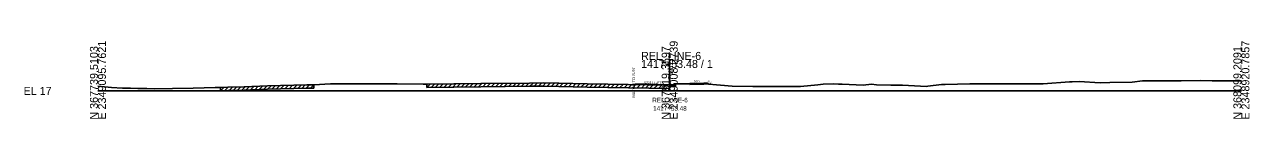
# Model space of a CAD drawing. Extents: x -26 to 403, y -10 to 6565.
# Drawn here: x -25.7 to 402.8, y -9.7 to 17.3 of the extents above; entities that cross this region are included whole.
import ezdxf

# ---------------------------------------------------------------- set-up
doc = ezdxf.new("R2010")
doc.units = 0
for name, color, linetype in [('RD_GPK_XS_Cell', 7, 'Continuous'), ('RD_XS_CurbBase', 7, 'Continuous'), ('RD_XS_CurbFront', 7, 'Continuous'), ('RD_XS_CurbTop', 7, 'Continuous'), ('RD_XS_EarthShd', 7, 'Continuous'), ('RD_XS_ExGround', 7, 'Continuous'), ('RD_XS_ExPaveRet', 7, 'Continuous'), ('RD_XS_MatchLine', 7, 'Continuous'), ('RD_XS_Pave', 7, 'Continuous'), ('RD_XS_SW', 7, 'Continuous'), ('RD_XS_SWbase', 7, 'Continuous'), ('RD_XS_TieSlope', 7, 'Continuous'), ('RD_XS_TX_Elev_EX', 7, 'Continuous'), ('RD_XS_TX_Elev_PR', 7, 'Continuous'), ('RD_XS_TX_MatchLine', 7, 'Continuous'), ('RD_XS_TX_Slope', 7, 'Continuous'), ('RD_XS_TX_Station', 7, 'Continuous'), ('RD_XS_TX_TOC', 7, 'Continuous')]:
    doc.layers.add(name, color=color, linetype=linetype)

msp = doc.modelspace()

# ---------------------------------------------------------------- linework, layer by layer
at = {"layer": 'RD_GPK_XS_Cell'}
for p, q in [((200, 0), (200, 10.79)), ((0, 0), (200, 0)), ((200, 0), (400, 0))]:
    msp.add_line(p, q, dxfattribs=at)
at = {"layer": 'RD_XS_CurbBase'}
for p, q in [((201.5, 1.52), (200, 1.6)), ((200, 0.54), (200, 1.6)), ((202, 1.52), (201.5, 1.52)), ((202, 2.52), (202, 1.52))]:
    msp.add_line(p, q, dxfattribs=at)
at = {"layer": 'RD_XS_CurbFront'}
msp.add_line((200, 1.6), (200, 2.1), dxfattribs=at)
at = {"layer": 'RD_XS_CurbTop'}
for p, q in [((200, 2.12), (200, 2.1)), ((200, 2.1), (201.42, 2.02)), ((201.42, 2.02), (201.5, 2.52)), ((201.5, 2.52), (202, 2.52))]:
    msp.add_line(p, q, dxfattribs=at)
at = {"layer": 'RD_XS_EarthShd'}
for p, q in [((202, 2.52), (207, 2.62)), ((212, 2.72), (213, 2.74))]:
    msp.add_line(p, q, dxfattribs=at)
at = {"layer": 'RD_XS_ExGround'}
msp.add_lwpolyline([(0, 1.7), (4.76, 1.24), (8.63, 0.98), (11.4, 0.98), (13.93, 0.87), (17.05, 0.82), (19.92, 0.73), (26.04, 0.84), (33.28, 0.93), (41.01, 1.17), (41.43, 1.21), (42.87, 1.18), (45.4, 1.3), (51.14, 1.46), (59.28, 1.72), (73.11, 2.08), (75.55, 2.14), (81.33, 2.44), (84.23, 2.5), (89.54, 2.5), (100.01, 2.5), (101.16, 2.5), (102.13, 2.5), (104.67, 2.47), (113.74, 2.41), (115.09, 2.38), (133.94, 2.57), (150.93, 2.75), (155.86, 2.8), (161.21, 2.68), (171.18, 2.5), (199.99, 1.97), (201.08, 1.91), (201.49, 1.89), (201.65, 2.39), (202.15, 2.39), (204.33, 2.43), (207.3, 2.5), (210.52, 2.5), (212.25, 2.53), (217.76, 2.06), (221.81, 1.71), (229.13, 1.57), (233.08, 1.52), (235.7, 1.5), (245.28, 1.5), (245.74, 1.5), (251.78, 2.08), (253.68, 2.38), (257.44, 2.47), (259.04, 2.39), (260.35, 2.3), (267.66, 2), (270.61, 2.37), (272.32, 2.14), (277.41, 2.04), (281.4, 2.05), (289.79, 1.57), (290.26, 1.61), (295.15, 2.21), (296.38, 2.22), (304.96, 2.46), (307.3, 2.46), (316.43, 2.51), (318.43, 2.51), (320.75, 2.53), (330.08, 2.51), (330.63, 2.52), (339.92, 3.16), (340.86, 3.19), (343.24, 3.26), (350.61, 2.84), (353.96, 2.9), (361.8, 3.07), (365.37, 3.52), (367.52, 3.52), (377.36, 3.51), (377.98, 3.49), (378.96, 3.53), (385.59, 3.6), (389.76, 3.5), (393.06, 3.5), (397.77, 3.53), (400, 3.55)], dxfattribs=at)
at = {"layer": 'RD_XS_ExPaveRet'}
for p, q in [((42.87, 0.04), (44.06, 1.24)), ((42.87, 0.04), (42.87, 1.18)), ((42.87, 0.04), (45.4, 0.16)), ((44.37, 0.11), (45.56, 1.3)), ((45.4, 0.16), (51.14, 0.32)), ((45.87, 0.17), (47.04, 1.35)), ((47.37, 0.21), (48.54, 1.39)), ((48.87, 0.26), (50.04, 1.43)), ((50.37, 0.3), (51.54, 1.48)), ((51.14, 0.32), (59.28, 0.58)), ((51.87, 0.34), (53.05, 1.52)), ((53.37, 0.39), (54.55, 1.57)), ((54.87, 0.44), (56.05, 1.62)), ((56.37, 0.49), (57.55, 1.67)), ((57.87, 0.53), (59.05, 1.71)), ((59.28, 0.58), (73.11, 0.94)), ((59.37, 0.58), (60.54, 1.75)), ((60.87, 0.62), (62.04, 1.79)), ((62.37, 0.66), (63.54, 1.83)), ((63.87, 0.7), (65.04, 1.87)), ((65.37, 0.74), (66.54, 1.91)), ((66.87, 0.77), (68.04, 1.95)), ((68.37, 0.81), (69.54, 1.99)), ((69.87, 0.85), (71.04, 2.03)), ((71.37, 0.89), (72.54, 2.07)), ((72.87, 0.93), (74.04, 2.1)), ((73.11, 0.94), (75.55, 0.99)), ((74.37, 0.97), (75.54, 2.14)), ((75.55, 2.14), (75.55, 0.99)), ((115.09, 1.24), (116.25, 2.39)), ((115.09, 1.24), (115.09, 2.38)), ((115.09, 1.24), (133.94, 1.43)), ((116.59, 1.25), (117.75, 2.41)), ((118.09, 1.27), (119.25, 2.42)), ((119.59, 1.28), (120.75, 2.44)), ((121.09, 1.3), (122.25, 2.45)), ((122.59, 1.31), (123.75, 2.47)), ((124.09, 1.33), (125.25, 2.48)), ((125.59, 1.34), (126.75, 2.5)), ((127.09, 1.36), (128.25, 2.51)), ((128.59, 1.37), (129.75, 2.53)), ((130.09, 1.39), (131.25, 2.54)), ((131.59, 1.4), (132.75, 2.56)), ((133.09, 1.42), (134.25, 2.57)), ((133.94, 1.43), (150.93, 1.61)), ((134.59, 1.43), (135.75, 2.59)), ((136.09, 1.45), (137.25, 2.61)), ((137.59, 1.47), (138.75, 2.62)), ((139.09, 1.48), (140.25, 2.64)), ((140.59, 1.5), (141.75, 2.65)), ((142.09, 1.51), (143.25, 2.67)), ((143.59, 1.53), (144.75, 2.68)), ((145.09, 1.54), (146.25, 2.7)), ((146.59, 1.56), (147.75, 2.71)), ((148.09, 1.58), (149.25, 2.73)), ((149.59, 1.59), (150.75, 2.75)), ((150.93, 1.61), (155.86, 1.66)), ((151.09, 1.61), (152.25, 2.76)), ((152.59, 1.62), (153.75, 2.78)), ((154.09, 1.64), (155.25, 2.8)), ((155.59, 1.66), (156.72, 2.78)), ((155.86, 1.66), (161.21, 1.54)), ((157.09, 1.63), (158.21, 2.75)), ((158.59, 1.6), (159.71, 2.72)), ((160.09, 1.57), (161.21, 2.68)), ((161.21, 1.54), (171.18, 1.36)), ((161.59, 1.53), (162.71, 2.66)), ((163.09, 1.51), (164.21, 2.63)), ((164.59, 1.48), (165.71, 2.6)), ((166.09, 1.45), (167.21, 2.58)), ((167.59, 1.43), (168.71, 2.55)), ((169.09, 1.4), (170.21, 2.52)), ((170.59, 1.37), (171.71, 2.49)), ((171.18, 1.36), (199.99, 0.83)), ((172.09, 1.34), (173.21, 2.47)), ((173.59, 1.32), (174.71, 2.44)), ((175.09, 1.29), (176.21, 2.41)), ((176.59, 1.26), (177.71, 2.38)), ((178.09, 1.23), (179.21, 2.36)), ((179.59, 1.21), (180.71, 2.33)), ((181.09, 1.18), (182.21, 2.3)), ((182.59, 1.15), (183.71, 2.27)), ((184.09, 1.12), (185.21, 2.24)), ((185.59, 1.09), (186.71, 2.22)), ((187.09, 1.07), (188.21, 2.19)), ((188.59, 1.04), (189.71, 2.16)), ((190.09, 1.01), (191.21, 2.13)), ((191.59, 0.98), (192.71, 2.1)), ((193.09, 0.95), (194.21, 2.08)), ((194.59, 0.93), (195.71, 2.05)), ((196.09, 0.9), (197.21, 2.02)), ((197.59, 0.87), (198.71, 1.99)), ((199.99, 1.97), (199.99, 0.83))]:
    msp.add_line(p, q, dxfattribs=at)
at = {"layer": 'RD_XS_MatchLine'}
msp.add_line((188, 2.46), (188, 2.19), dxfattribs=at)
at = {"layer": 'RD_XS_Pave'}
msp.add_line((188, 2.46), (200, 2.12), dxfattribs=at)
at = {"layer": 'RD_XS_SW'}
msp.add_line((207, 2.62), (212, 2.72), dxfattribs=at)
at = {"layer": 'RD_XS_SWbase'}
for p, q in [((207, 2.28), (207, 2.62)), ((212, 2.38), (207, 2.28)), ((212, 2.72), (212, 2.38))]:
    msp.add_line(p, q, dxfattribs=at)
at = {"layer": 'RD_XS_TieSlope'}
msp.add_line((213, 2.74), (213.65, 2.41), dxfattribs=at)

# ---------------------------------------------------------------- texts
at = {"layer": 'RD_GPK_XS_Cell'}
for s, p in [('E 2349095.7621', (2.8, -10)), ('E 2349008.2739', (202.8, -10)), ('E 2348920.7857', (402.8, -10)), ('N 367739.5103', (0, -10)), ('N 367919.3597', (200, -10)), ('N 368099.2091', (400, -10))]:
    msp.add_text(s, height=2.8, rotation=90, dxfattribs=at).set_placement(p)
for s, p in [('REL_LINE-6', (190, 10.79)), ('1417+53.48 / 1', (190, 7.99)), ('EL 17', (-26, -1.4))]:
    msp.add_text(s, height=2.8, dxfattribs=at).set_placement(p)
at = {"layer": 'RD_XS_TX_Elev_EX'}
msp.add_text('18.97', height=1, rotation=90, dxfattribs=at).set_placement((200.5, 1.97))
at = {"layer": 'RD_XS_TX_Elev_PR'}
msp.add_text(' 19.12', height=1.2, rotation=90, dxfattribs=at).set_placement((201.2, 5.2))
at = {"layer": 'RD_XS_TX_MatchLine'}
msp.add_text('MATCH TO S-97', height=1, rotation=90, dxfattribs=at).set_placement((187.92, -2.31))
at = {"layer": 'RD_XS_TX_Slope'}
for s, rotation, p in [('0.028 FT./FT.', 358.3961, (190.98, 2.62)), ('50:1', 1.1458, (208.54, 3.04)), ('2:1', 333.4349, (213.2, 3.11))]:
    msp.add_text(s, height=0.75, rotation=rotation, dxfattribs=at).set_placement(p)
at = {"layer": 'RD_XS_TX_Station'}
for s, p in [('REL_LINE-6', (193.92, -3.98)), ('1417+53.48', (194.23, -6.88))]:
    msp.add_text(s, height=1.6, dxfattribs=at).set_placement(p)
at = {"layer": 'RD_XS_TX_TOC'}
msp.add_text('TOCRT', height=0.05, dxfattribs=at).set_placement((201.22, 2.47))

doc.saveas('drawing.dxf')
